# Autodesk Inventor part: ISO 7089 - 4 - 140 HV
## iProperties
Library Location: C:\Program Files\Autodesk\Inventor 6\content
Library: local
SubLibrary: ISO
Family: 62
Member: 60
Member Major Revision: 1
Member Minor Revision: 1
Comments: To add or edit properties for Autodesk Inventor files, use iProperties.
Created: 2003-05
Part Number: ISO 7089 - 4 - 140 HV
Vendor: Autodesk Inc.
Document SubType Name: Modeling
Designer: Philippe
Description: Rondelle
Standard: ISO 7089 4 - 140 HV
Alert: To add or edit properties for Autodesk Inventor files, use iProperties.
Control State: 0
Master: False
Checked Out: False
Shininess: 64.0
Length Units: 11269
Angle Units: 11279
Time Units: 11290
Mass Units: 11283
Length Display Precision: 3
Angle Display Precision: 2
Compacted: True
Classification: un/spsc 31161807
Density: 0.0
Volumn: 0.0
Area: 0.0
PropertySet Name: Model Information
Author: Philippe
Revision Number: 1
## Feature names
1. Corps [Extrusion]
